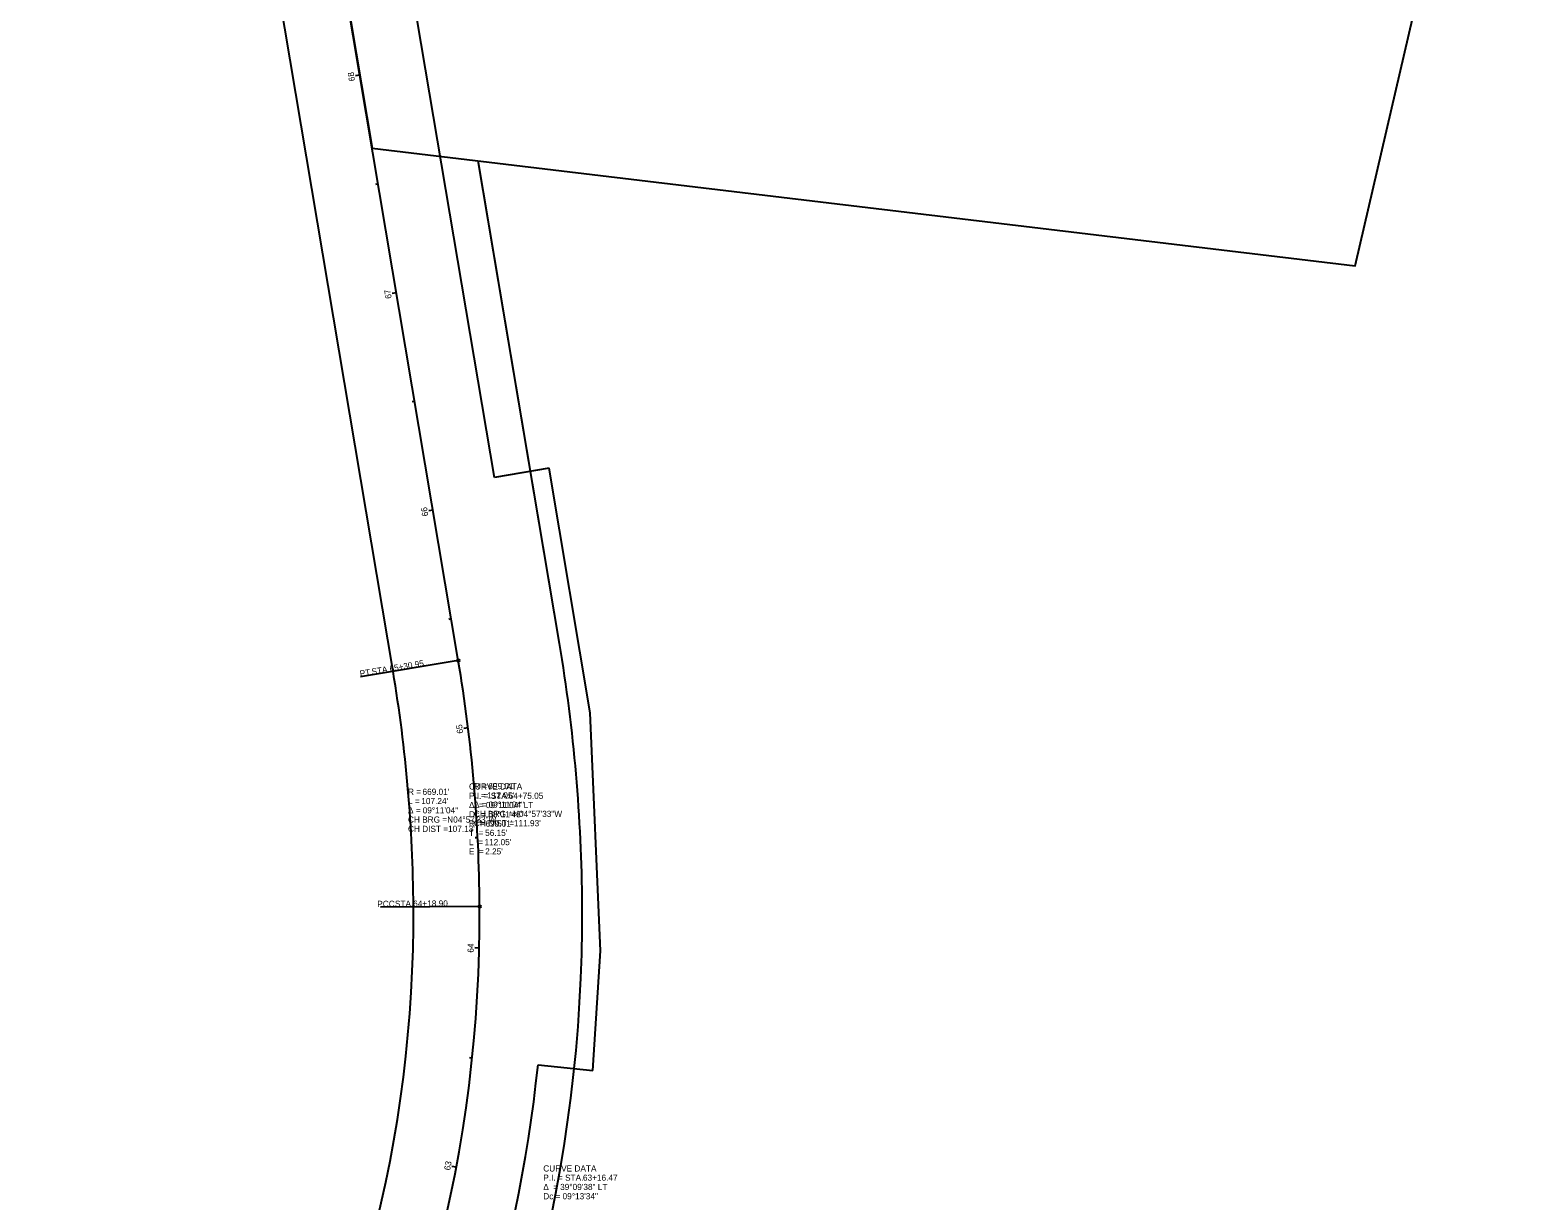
# Model space of a CAD drawing. Extents: x 2346746 to 2349554, y 247132 to 249252.
# Drawn here: x 2347467 to 2348150, y 248191 to 248721 of the extents above; entities that cross this region are included whole.
import ezdxf

# ---------------------------------------------------------------- set-up
doc = ezdxf.new("R2010")
doc.units = 0
for name, color, linetype in [('_CIVIL_CONSTRUCTION', 7, 'Continuous'), ('Default', 7, 'Continuous'), ('UT_X_FO', 7, 'Continuous'), ('UT_X_Telecom', 7, 'Continuous'), ('V-SURV-ANNO', 7, 'Continuous'), ('V-TOPO-ANNO', 7, 'Continuous'), ('V-TOPO-BNDY', 7, 'Continuous'), ('V-TOPO-FEAT', 7, 'Continuous'), ('V-UTIL-WATR-LINE-ANNO', 7, 'Continuous')]:
    doc.layers.add(name, color=color, linetype=linetype)

msp = doc.modelspace()

# ---------------------------------------------------------------- linework, layer by layer
at = {"layer": '_CIVIL_CONSTRUCTION'}
for p, q in [((2347660.65, 248435.6), (2347616.28, 248428.14)), ((2347670.33, 248324.09), (2347625.33, 248323.81))]:
    msp.add_line(p, q, dxfattribs=at)
for centre in [(2347660.65, 248435.6), (2347670.33, 248324.09)]:
    msp.add_circle(centre, 0.6, dxfattribs=at)
at = {"layer": 'UT_X_FO'}
msp.add_line((2347660.65, 248435.6), (2347525.54, 249238.58), dxfattribs=at)
for centre, radius, start, end in [((2346971.33, 248319.62), 699.01, 0.36691, 9.55135), ((2347049.33, 248320.12), 621.01, 330.3908, 0.36691)]:
    msp.add_arc(centre, radius, start, end, dxfattribs=at)
at = {"layer": 'V-SURV-ANNO'}
for p, q in [((2347616.01, 248700.92), (2347614.04, 248700.59)), ((2347624.31, 248651.62), (2347623.12, 248651.42)), ((2347632.6, 248602.31), (2347630.63, 248601.98)), ((2347640.9, 248553), (2347639.72, 248552.8)), ((2347649.2, 248503.7), (2347647.22, 248503.36)), ((2347657.49, 248454.39), (2347656.31, 248454.19)), ((2347665.11, 248404.98), (2347663.13, 248404.73)), ((2347669.44, 248355.18), (2347668.24, 248355.12)), ((2347670.16, 248305.19), (2347668.16, 248305.24)), ((2347666.95, 248255.31), (2347665.76, 248255.44)), ((2347659.74, 248205.85), (2347657.77, 248206.22))]:
    msp.add_line(p, q, dxfattribs=at)
at = {"layer": 'V-TOPO-ANNO'}
msp.add_lwpolyline([(2346864.44, 249252.04), (2347525.54, 249238.58), (2347621.59, 248667.77), (2348067.21, 248614.43), (2348211.26, 249235.08), (2349553.92, 249207.61), (2349518.11, 247171.02), (2347341.77, 247208.55)], dxfattribs=at)
at = {"layer": 'V-TOPO-BNDY'}
for p, q in [((2347631.07, 248430.63), (2347495.01, 249239.2)), ((2347677.12, 248518.55), (2347555.54, 249237.97)), ((2347677.12, 248518.55), (2347555.54, 249237.97)), ((2347677.12, 248518.55), (2347555.54, 249237.97)), ((2347701.77, 248522.7), (2347677.12, 248518.55)), ((2347701.77, 248522.7), (2347677.12, 248518.55)), ((2347701.77, 248522.7), (2347677.12, 248518.55)), ((2347720.43, 248411.82), (2347701.77, 248522.7)), ((2347720.43, 248411.82), (2347701.77, 248522.7)), ((2347720.43, 248411.82), (2347701.77, 248522.7)), ((2347725.15, 248303.97), (2347720.43, 248411.82)), ((2347725.15, 248303.97), (2347720.43, 248411.82)), ((2347725.15, 248303.97), (2347720.43, 248411.82)), ((2347721.66, 248249.67), (2347725.15, 248303.97)), ((2347721.66, 248249.67), (2347725.15, 248303.97)), ((2347721.66, 248249.67), (2347725.15, 248303.97)), ((2347696.8, 248252.27), (2347721.66, 248249.67)), ((2347696.8, 248252.27), (2347721.66, 248249.67)), ((2347696.8, 248252.27), (2347721.66, 248249.67))]:
    msp.add_line(p, q, dxfattribs=at)
for centre, radius, start, end in [((2346971.33, 248319.62), 669.01, 0.36691, 9.55135), ((2347049.33, 248320.12), 591.01, 330.3908, 0.36691), ((2347049.33, 248320.12), 651.01, 330.3908, 354.01806), ((2347049.33, 248320.12), 651.01, 330.3908, 354.01806)]:
    msp.add_arc(centre, radius, start, end, dxfattribs=at)
at = {"layer": 'V-TOPO-FEAT'}
for q in [(2347669.67, 248662.29), (2347669.71, 248662.01)]:
    msp.add_line((2347706.51, 248443.32), q, dxfattribs=at)
for centre, radius, start, end in [((2346971.33, 248319.62), 745.51, 0.36691, 9.55135), ((2346971.33, 248319.62), 745.51, 0.36691, 9.55135), ((2347049.33, 248320.12), 667.51, 330.3908, 0.36691), ((2347049.33, 248320.12), 667.51, 330.3908, 0.36691)]:
    msp.add_arc(centre, radius, start, end, dxfattribs=at)

# ---------------------------------------------------------------- texts
at = {"layer": '_CIVIL_CONSTRUCTION'}
for s, rotation, p in [('65+30.95', 9.55135, (2347629.72, 248430.44)), ('PT', 9.55135, (2347616.24, 248428.17)), (' STA. ', 9.55135, (2347620.53, 248428.89)), ('PCC', 0.36691, (2347623.93, 248323.83)), (' STA. ', 0.36691, (2347630.89, 248323.88)), ('64+18.90', 0.36691, (2347640.21, 248323.94))]:
    msp.add_text(s, height=2.8, rotation=rotation, dxfattribs=at).set_placement(p)
at = {"layer": 'Default'}
for s, p in [('R = ', (2347637.84, 248374.65)), ('L = ', (2347637.84, 248370.45)), ("107.24'", (2347643.88, 248370.45)), ("669.01'", (2347644.43, 248374.65)), ('Δ = ', (2347637.84, 248366.25)), ('09°11\'04"', (2347644.52, 248366.25)), ('CH BRG = ', (2347637.84, 248362.05)), ('CH DIST = ', (2347637.84, 248357.85)), ('N04°57\'33"W', (2347655.62, 248362.05)), ("107.13'", (2347656.02, 248357.85))]:
    msp.add_text(s, height=2.8, dxfattribs=at).set_placement(p)
at = {"layer": 'UT_X_Telecom'}
for s, p in [('CURVE DATA', (2347665.49, 248377.05)), ('P.I. = STA. ', (2347665.49, 248372.85)), ('64+75.05', (2347683.48, 248372.85)), ('Δ  = ', (2347665.49, 248368.65)), ('Dc = ', (2347665.49, 248364.45)), ('09°11\'04" LT', (2347673.14, 248368.65)), ('08°11\'48"', (2347674.24, 248364.45)), ('R  = ', (2347665.49, 248360.25)), ("699.01'", (2347673.03, 248360.25)), ('T  = ', (2347665.49, 248356.05)), ('L  = ', (2347665.49, 248351.85)), ("112.05'", (2347672.53, 248351.85)), ("56.15'", (2347672.81, 248356.05)), ('E  = ', (2347665.49, 248347.65)), ("2.25'", (2347672.83, 248347.65)), ('CURVE DATA', (2347699.17, 248203.91)), ('P.I. = STA. ', (2347699.17, 248199.71)), ('63+16.47', (2347717.16, 248199.71)), ('Δ  = ', (2347699.17, 248195.51)), ('39°09\'38" LT', (2347706.81, 248195.51)), ('Dc = ', (2347699.17, 248191.31)), ('09°13\'34"', (2347707.91, 248191.31))]:
    msp.add_text(s, height=2.8, dxfattribs=at).set_placement(p)
at = {"layer": 'V-SURV-ANNO'}
for s, rotation, p in [('68', 99.55135, (2347613.9, 248698.41)), ('67', 99.55135, (2347630.49, 248599.8)), ('66', 99.55135, (2347647.09, 248501.17)), ('65', 97.01438, (2347662.89, 248402.6)), ('64', 88.62309, (2347667.61, 248303.09)), ('63', 79.39685, (2347656.9, 248204.26))]:
    msp.add_text(s, height=2.8, rotation=rotation, dxfattribs=at).set_placement(p)
at = {"layer": 'V-UTIL-WATR-LINE-ANNO'}
for s, p in [('R = ', (2347667.73, 248377.24)), ("699.01'", (2347674.27, 248377.24)), ('L = ', (2347667.73, 248373.04)), ("112.05'", (2347673.77, 248373.04)), ('Δ = ', (2347667.73, 248368.84)), ('CH BRG = ', (2347667.73, 248364.64)), ('09°11\'04"', (2347674.38, 248368.84)), ('N04°57\'33"W', (2347685.44, 248364.64)), ('CH DIST = ', (2347667.73, 248360.44)), ("111.93'", (2347685.87, 248360.44))]:
    msp.add_text(s, height=2.8, dxfattribs=at).set_placement(p)

doc.saveas('drawing.dxf')
